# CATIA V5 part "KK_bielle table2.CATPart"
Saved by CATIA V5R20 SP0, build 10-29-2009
Part number: bielle table 2
Bounding box of the stored display mesh (mm): x -1002.373 to 342.501, y -156.493 to -111.493, z 0 to 90
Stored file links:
  G:\Khaled_CFAO_2011\ST2M\ST2M_GR2\tcorbin\Khaled\CAD_ThinkMOTION\KK_bielle table2.CATPart
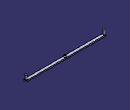
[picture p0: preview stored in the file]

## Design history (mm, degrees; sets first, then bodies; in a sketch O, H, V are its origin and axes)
Body1 (main body)
  Sketch1 on xy-plane, origin (0, 0, 0), H (1, 0, 0), V (0, 1, 0)
    line L1 (-979.9356, -111.4934) -> (320.0644, -111.4934)
    arc A1 centre (320.0644, -133.9934) radius 22.5 from (320.0644, -111.4934) to (320.0644, -156.4934) cw
    line L2 (320.0644, -156.4934) -> (-979.9356, -156.4934)
    arc A2 centre (-979.9356, -133.9934) radius 22.5 from (-979.9356, -156.4934) to (-979.9356, -111.4934) cw
    length L1 = 1300
    distance L1 L2 = 45
    length L2 = 1300
    tangency: A1 L1, L2 A1, A2 L2
    horizontal: L1 H, L2 H
  Pad1: profile Sketch1, direction (0, 0, 1), length 20
  Sketch2 on end face of Pad1, origin (0, 0, 20), H (1, 0, 0), V (0, 1, 0)
    circle A1 centre (320.0644, -133.9934) radius 15
    reference projected arc E1 centre (320.0644, -133.9934) radius 22.5 from (320.0644, -156.4934) to (320.0644, -111.4934) ccw from edge [face of Pad1 from Sketch1.A1 | end face of Pad1]
    circle A2 centre (-979.9356, -133.9934) radius 15
    reference projected arc E2 centre (-979.9356, -133.9934) radius 22.5 from (-979.9356, -111.4934) to (-979.9356, -156.4934) ccw from edge [face of Pad1 from Sketch1.A2 | end face of Pad1]
    concentricity: A1 E1, A2 E2
  Pad2: profile Sketch2, direction (0, 0, 1), length 70
  Sketch3 on end face of Pad1, origin (-305.2924, -144.6, 20), H (1, 0, 0), V (0, 1, 0)
    point P1 (-24.6432, 10.6066)
    reference projected line E1 (-674.6432, -11.8934) -> (625.3568, -11.8934) from edge [face of Pad1 from Sketch1.L2 | end face of Pad1]
    reference projected circle E2 centre (625.3568, 10.6066) radius 15 from edge [face of Pad2 from Sketch2.A1 | end face of Pad2]
    distance P1 E1 = 22.5
    distance P1 E2 = 665
  Hole1: placed by Sketch3, at (-329.9356, -133.9934, 20) direction (0, 0, -1), diameter 30, through (limit type 3)
  Boundary1: Boundary face of Pad2 from Sketch2.A2
  Extract1: ExtractElem edge of Boundary1
  Boundary2: Boundary face of Pad2 from Sketch2.A1
  Extract2: ExtractElem edge of Boundary2
  Boundary3: Boundary face of Hole1
  Extract3: ExtractElem edge of Boundary3
  Pad3: profile Extract3, length 50
  Fillet1: radius 5, on end face of Pad3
